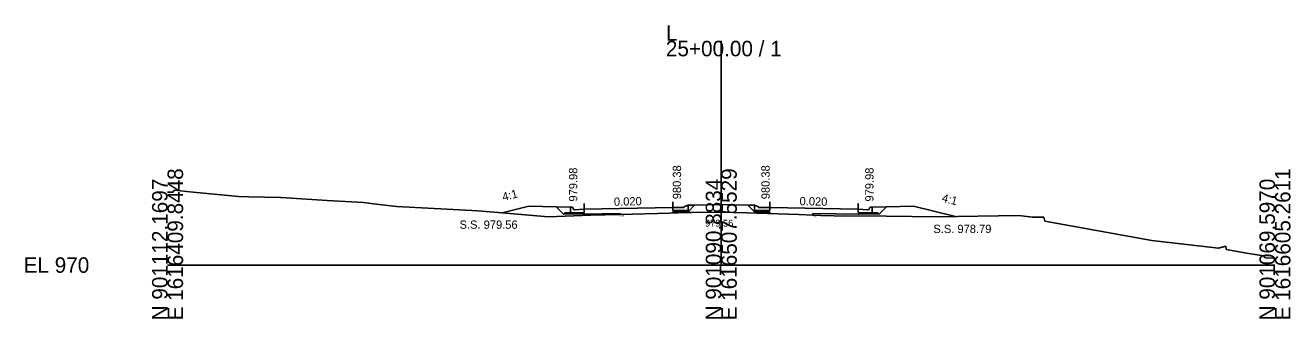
# Model space of a CAD drawing. Extents: x 1009 to 7438, y -1586 to 7964.
# Drawn here: x 2009.2 to 2237.7, y 2914 to 2967.1 of the extents above; entities that cross this region are included whole.
import ezdxf

# ---------------------------------------------------------------- set-up
doc = ezdxf.new("R2010")
doc.units = 0
for name, color, linetype in [('Exist Cross Section Cell', 7, 'Continuous'), ('Exist XS Center Line Elevation Label', 7, 'Continuous'), ('Exist XS Ground Line', 7, 'Continuous'), ('Prop XS Dump Level', 7, 'Continuous'), ('Prop XS Earthwork Shape', 7, 'Continuous'), ('Prop XS EOT Tick Mark', 7, 'Continuous'), ('Prop XS Finish Grade', 7, 'Continuous'), ('Prop XS Finish Grade CurbGutter', 7, 'Continuous'), ('Prop XS Finish Grade Earthwork', 7, 'Continuous'), ('Prop XS Finish Grade Pavement', 7, 'Continuous'), ('Prop XS Hydro Elevations', 7, 'Continuous'), ('Prop XS Pvmt Edge Slope', 7, 'Continuous'), ('Prop XS SE Text', 7, 'Continuous'), ('Prop XS Side Slope Text', 7, 'Continuous'), ('Prop XS SS Elevation Text', 7, 'Continuous'), ('Prop XS Subgrade CurbGutter', 7, 'Continuous'), ('Prop XS Subgrade Earthwork', 7, 'Continuous')]:
    doc.layers.add(name, color=color, linetype=linetype)

msp = doc.modelspace()

# ---------------------------------------------------------------- linework, layer by layer
at = {"layer": 'Exist Cross Section Cell'}
for p, q in [((2134.89, 2923.73), (2134.89, 2964.26)), ((2034.89, 2923.73), (2134.89, 2923.73)), ((2134.89, 2923.73), (2234.89, 2923.73))]:
    msp.add_line(p, q, dxfattribs=at)
at = {"layer": 'Exist XS Ground Line'}
for p, q in [((2034.89, 2936.9), (2035.9, 2936.89)), ((2035.9, 2936.89), (2036.09, 2937.24)), ((2036.09, 2937.24), (2039.49, 2936.92)), ((2039.49, 2936.92), (2047.73, 2936.13)), ((2047.73, 2936.13), (2049.58, 2936.09)), ((2049.58, 2936.09), (2055.31, 2935.93)), ((2055.31, 2935.93), (2056.29, 2935.87)), ((2056.29, 2935.87), (2063.74, 2935.4)), ((2063.74, 2935.4), (2070.26, 2935.05)), ((2070.26, 2935.05), (2072.09, 2934.78)), ((2072.09, 2934.78), (2076.26, 2934.33)), ((2076.26, 2934.33), (2089.86, 2933.58)), ((2089.86, 2933.58), (2090.87, 2933.52)), ((2090.87, 2933.52), (2093.9, 2933.27)), ((2093.9, 2933.27), (2103.72, 2932.47)), ((2103.72, 2932.47), (2111.26, 2932.72)), ((2111.26, 2932.72), (2116.63, 2932.84)), ((2116.63, 2932.84), (2125.63, 2933.14)), ((2125.63, 2933.14), (2128.63, 2933.25)), ((2128.63, 2933.25), (2129.52, 2933.26)), ((2129.52, 2933.26), (2133.62, 2933.32)), ((2133.62, 2933.32), (2134.97, 2933.29)), ((2134.97, 2933.29), (2139.51, 2933.2)), ((2139.51, 2933.2), (2148.9, 2932.86)), ((2148.9, 2932.86), (2151.49, 2932.77)), ((2151.49, 2932.77), (2152.89, 2932.66)), ((2152.89, 2932.66), (2155.28, 2932.64)), ((2155.28, 2932.64), (2164.7, 2932.55)), ((2164.7, 2932.55), (2173.88, 2932.43)), ((2173.88, 2932.43), (2188.66, 2932.67)), ((2188.66, 2932.67), (2191.1, 2932.4)), ((2191.1, 2932.4), (2193.14, 2932.38)), ((2193.14, 2932.38), (2193.31, 2931.65)), ((2193.31, 2931.65), (2212.68, 2928.2)), ((2212.68, 2928.2), (2224.68, 2926.81)), ((2224.68, 2926.81), (2225.99, 2927.12)), ((2225.99, 2927.12), (2226.09, 2926.56)), ((2226.09, 2926.56), (2229.47, 2925.96)), ((2229.47, 2925.96), (2232.83, 2925.37)), ((2232.83, 2925.37), (2233.12, 2925.03)), ((2233.12, 2925.03), (2234.89, 2924.98))]:
    msp.add_line(p, q, dxfattribs=at)
at = {"layer": 'Prop XS Dump Level'}
for p, q in [((2110.14, 2933.83), (2126.14, 2934.15)), ((2110.14, 2933.83), (2126.14, 2934.15)), ((2143.64, 2934.15), (2159.64, 2933.83)), ((2143.64, 2934.15), (2159.64, 2933.83))]:
    msp.add_line(p, q, dxfattribs=at)
at = {"layer": 'Prop XS Earthwork Shape'}
for points in [[(2110.14, 2932.91), (2110.14, 2933), (2106.39, 2932.92), (2105.05, 2934.26), (2100.14, 2934.37), (2095.3, 2933.16), (2103.72, 2932.47), (2111.26, 2932.72), (2116.62, 2932.84), (2116.62, 2933.04)], [(2126.14, 2933.23), (2126.14, 2933.32), (2128.89, 2933.37), (2130.07, 2934.55), (2130.12, 2934.55), (2134.89, 2934.65), (2139.67, 2934.55), (2139.72, 2934.55), (2140.9, 2933.37), (2143.64, 2933.32), (2143.64, 2933.23), (2143.64, 2933.05), (2139.51, 2933.2), (2134.97, 2933.29), (2133.62, 2933.32), (2129.52, 2933.26), (2128.63, 2933.25), (2126.14, 2933.16)], [(2151.42, 2933.08), (2151.42, 2932.77), (2151.49, 2932.77), (2152.89, 2932.66), (2155.28, 2932.64), (2164.7, 2932.55), (2173.88, 2932.43), (2177.17, 2932.49), (2169.64, 2934.37), (2164.73, 2934.26), (2163.39, 2932.92), (2159.64, 2933), (2159.64, 2932.91)]]:
    msp.add_lwpolyline(points, close=True, dxfattribs=at)
at = {"layer": 'Prop XS EOT Tick Mark'}
for p, q in [((2110.14, 2933.83), (2110.14, 2934.83)), ((2126.14, 2934.15), (2126.14, 2935.15)), ((2143.64, 2934.15), (2143.64, 2935.15)), ((2159.64, 2933.83), (2159.64, 2934.83))]:
    msp.add_line(p, q, dxfattribs=at)
at = {"layer": 'Prop XS Finish Grade'}
for p, q in [((2128.89, 2934.53), (2130.12, 2934.55)), ((2140.89, 2934.53), (2139.67, 2934.55)), ((2107.64, 2934.21), (2105.05, 2934.26)), ((2162.14, 2934.21), (2164.73, 2934.26))]:
    msp.add_line(p, q, dxfattribs=at)
at = {"layer": 'Prop XS Finish Grade CurbGutter'}
for p, q in [((2128.14, 2934.28), (2128.89, 2934.53)), ((2141.64, 2934.28), (2140.89, 2934.53)), ((2107.64, 2934.21), (2107.89, 2934.21)), ((2107.89, 2934.21), (2108.02, 2934.18)), ((2108.11, 2934.09), (2108.02, 2934.18)), ((2108.18, 2933.84), (2108.11, 2934.09)), ((2108.27, 2933.75), (2108.18, 2933.84)), ((2108.39, 2933.72), (2108.27, 2933.75)), ((2110.14, 2933.83), (2108.39, 2933.72)), ((2126.14, 2934.15), (2128.14, 2934.11)), ((2128.14, 2934.11), (2128.14, 2934.28)), ((2141.64, 2934.11), (2141.64, 2934.28)), ((2143.64, 2934.15), (2141.64, 2934.11)), ((2159.64, 2933.83), (2161.39, 2933.72)), ((2161.39, 2933.72), (2161.52, 2933.75)), ((2161.52, 2933.75), (2161.61, 2933.84)), ((2161.61, 2933.84), (2161.68, 2934.09)), ((2161.68, 2934.09), (2161.77, 2934.18)), ((2161.89, 2934.21), (2161.77, 2934.18)), ((2162.14, 2934.21), (2161.89, 2934.21))]:
    msp.add_line(p, q, dxfattribs=at)
at = {"layer": 'Prop XS Finish Grade Earthwork'}
for p, q in [((2100.14, 2934.37), (2095.3, 2933.16)), ((2105.05, 2934.26), (2100.14, 2934.37)), ((2130.12, 2934.55), (2134.89, 2934.65)), ((2134.89, 2934.65), (2139.67, 2934.55)), ((2164.73, 2934.26), (2169.64, 2934.37)), ((2169.64, 2934.37), (2177.17, 2932.49))]:
    msp.add_line(p, q, dxfattribs=at)
at = {"layer": 'Prop XS Finish Grade Pavement'}
for p, q in [((2110.14, 2933.83), (2126.14, 2934.15)), ((2143.64, 2934.15), (2159.64, 2933.83))]:
    msp.add_line(p, q, dxfattribs=at)
at = {"layer": 'Prop XS Pvmt Edge Slope'}
for p, q in [((2106.64, 2933.18), (2106.39, 2932.92)), ((2107.64, 2933.2), (2106.64, 2933.18)), ((2127.64, 2933.6), (2128.89, 2933.62)), ((2128.64, 2933.62), (2128.89, 2933.37)), ((2142.14, 2933.6), (2140.89, 2933.62)), ((2141.14, 2933.62), (2140.9, 2933.37)), ((2162.14, 2933.2), (2163.14, 2933.18)), ((2163.14, 2933.18), (2163.39, 2932.92))]:
    msp.add_line(p, q, dxfattribs=at)
at = {"layer": 'Prop XS Subgrade CurbGutter'}
for p, q in [((2128.89, 2933.62), (2128.89, 2934.53)), ((2140.89, 2933.62), (2140.89, 2934.53)), ((2107.64, 2933.2), (2107.64, 2934.21)), ((2110.14, 2933.25), (2107.64, 2933.2)), ((2110.14, 2933.83), (2110.14, 2933.25)), ((2126.14, 2934.15), (2126.14, 2933.57)), ((2126.14, 2933.57), (2127.64, 2933.6)), ((2143.64, 2933.57), (2142.14, 2933.6)), ((2143.64, 2934.15), (2143.64, 2933.57)), ((2159.64, 2933.83), (2159.64, 2933.25)), ((2159.64, 2933.25), (2162.14, 2933.2)), ((2162.14, 2933.2), (2162.14, 2934.21))]:
    msp.add_line(p, q, dxfattribs=at)
at = {"layer": 'Prop XS Subgrade Earthwork'}
for p, q in [((2128.89, 2933.37), (2130.07, 2934.55)), ((2140.9, 2933.37), (2139.72, 2934.55)), ((2106.39, 2932.92), (2105.05, 2934.26)), ((2110.14, 2933), (2106.39, 2932.92)), ((2116.62, 2933.04), (2110.14, 2932.91)), ((2110.14, 2932.91), (2110.14, 2933)), ((2116.62, 2933.04), (2116.62, 2932.84)), ((2126.14, 2933.32), (2128.89, 2933.37)), ((2126.14, 2933.23), (2126.14, 2933.32)), ((2126.14, 2933.23), (2126.14, 2933.16)), ((2143.64, 2933.32), (2140.9, 2933.37)), ((2143.64, 2933.23), (2143.64, 2933.32)), ((2143.64, 2933.23), (2143.64, 2933.05)), ((2151.42, 2933.08), (2151.42, 2932.77)), ((2151.42, 2933.08), (2159.64, 2932.91)), ((2159.64, 2932.91), (2159.64, 2933)), ((2159.64, 2933), (2163.39, 2932.92)), ((2163.39, 2932.92), (2164.73, 2934.26))]:
    msp.add_line(p, q, dxfattribs=at)

# ---------------------------------------------------------------- texts
at = {"layer": 'Exist Cross Section Cell'}
for s, p in [('L', (2124.89, 2964.26)), ('25+00.00 / 1', (2124.89, 2961.46)), ('EL 970', (2008.89, 2922.33))]:
    msp.add_text(s, height=2.8, dxfattribs=at).set_placement(p)
for s, p in [('N 901112.1697', (2034.89, 2913.73)), ('E 1616409.8448', (2037.69, 2913.73)), ('N 901090.8834', (2134.89, 2913.73)), ('E 1616507.5529', (2137.69, 2913.73)), ('N 901069.5970', (2234.89, 2913.73)), ('E 1616605.2611', (2237.69, 2913.73))]:
    msp.add_text(s, height=2.8, rotation=90, dxfattribs=at).set_placement(p)
at = {"layer": 'Exist XS Center Line Elevation Label'}
msp.add_text('979.56', height=1.25, dxfattribs=at).set_placement((2131.96, 2930.67))
at = {"layer": 'Prop XS Dump Level'}
for p in [(2116.62, 2932.54), (2116.62, 2932.54), (2151.42, 2932.47), (2151.42, 2932.47)]:
    msp.add_text('Eop', height=0.3, dxfattribs=at).set_placement(p)
at = {"layer": 'Prop XS Hydro Elevations'}
for s, p in [('979.98', (2108.89, 2935.21)), ('980.38', (2127.64, 2935.63)), ('980.38', (2143.64, 2935.63)), ('979.98', (2162.39, 2935.21))]:
    msp.add_text(s, height=1.5, rotation=90, dxfattribs=at).set_placement(p)
at = {"layer": 'Prop XS SE Text'}
for rotation, p in [(1.1458, (2115.52, 2934.44)), (358.8542, (2149.02, 2934.54))]:
    msp.add_text('0.020', height=1.5, rotation=rotation, dxfattribs=at).set_placement(p)
at = {"layer": 'Prop XS Side Slope Text'}
for rotation, p in [(14.0362, (2095.54, 2935.3)), (345.9638, (2174.63, 2935.21))]:
    msp.add_text('4:1', height=1.5, rotation=rotation, dxfattribs=at).set_placement(p)
at = {"layer": 'Prop XS SS Elevation Text'}
for s, p in [('S.S. 979.56', (2087.63, 2930.29)), ('S.S. 978.79', (2173.2, 2929.52))]:
    msp.add_text(s, height=1.5, dxfattribs=at).set_placement(p)

doc.saveas('drawing.dxf')
